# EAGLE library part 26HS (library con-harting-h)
CONNECTOR
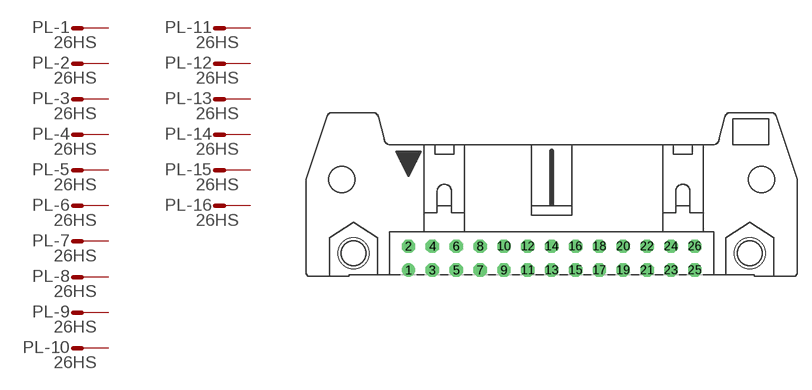
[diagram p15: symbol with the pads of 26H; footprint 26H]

Designator prefix PL; gates -1=M -2=M -3=M -4=M -5=M -6=M -7=M -8=M -9=M -10=M -11=M -12=M -13=M -14=M -15=M -16=M -17=M -18=M -19=M -20=M -21=M -22=M -23=M -24=M -25=M -26=M

## 26HS (OC_FARNELL: unknown; OC_NEWARK: unknown)  [26H]
1  -1:S  pas
2  -2:S  pas
3  -3:S  pas
4  -4:S  pas
5  -5:S  pas
6  -6:S  pas
7  -7:S  pas
8  -8:S  pas
9  -9:S  pas
10  -10:S  pas
11  -11:S  pas
12  -12:S  pas
13  -13:S  pas
14  -14:S  pas
15  -15:S  pas
16  -16:S  pas
17  -17:S  pas
18  -18:S  pas
19  -19:S  pas
20  -20:S  pas
21  -21:S  pas
22  -22:S  pas
23  -23:S  pas
24  -24:S  pas
25  -25:S  pas
26  -26:S  pas

## Footprint 26H (pad centres in mm)
CONNECTOR
drill 0.914 round: 1 -15.24,-1.27
drill 0.914 octagon: 2 -15.24,1.27; 3 -12.7,-1.27; 4 -12.7,1.27; 5 -10.16,-1.27; 6 -10.16,1.27; 7 -7.62,-1.27; 8 -7.62,1.27; 9 -5.08,-1.27; 10 -5.08,1.27; 11 -2.54,-1.27; 12 -2.54,1.27; 13 0,-1.27; 14 0,1.27; 15 2.54,-1.27; 16 2.54,1.27; 17 5.08,-1.27; 18 5.08,1.27; 19 7.62,-1.27; 20 7.62,1.27; 21 10.16,-1.27; 22 10.16,1.27; 23 12.7,-1.27; 24 12.7,1.27; 25 15.24,-1.27; 26 15.24,1.27
hole 3.302 at -21.082,0.533
hole 3.302 at 21.082,0.533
